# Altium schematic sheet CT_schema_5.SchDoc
size 376 x 215 mm
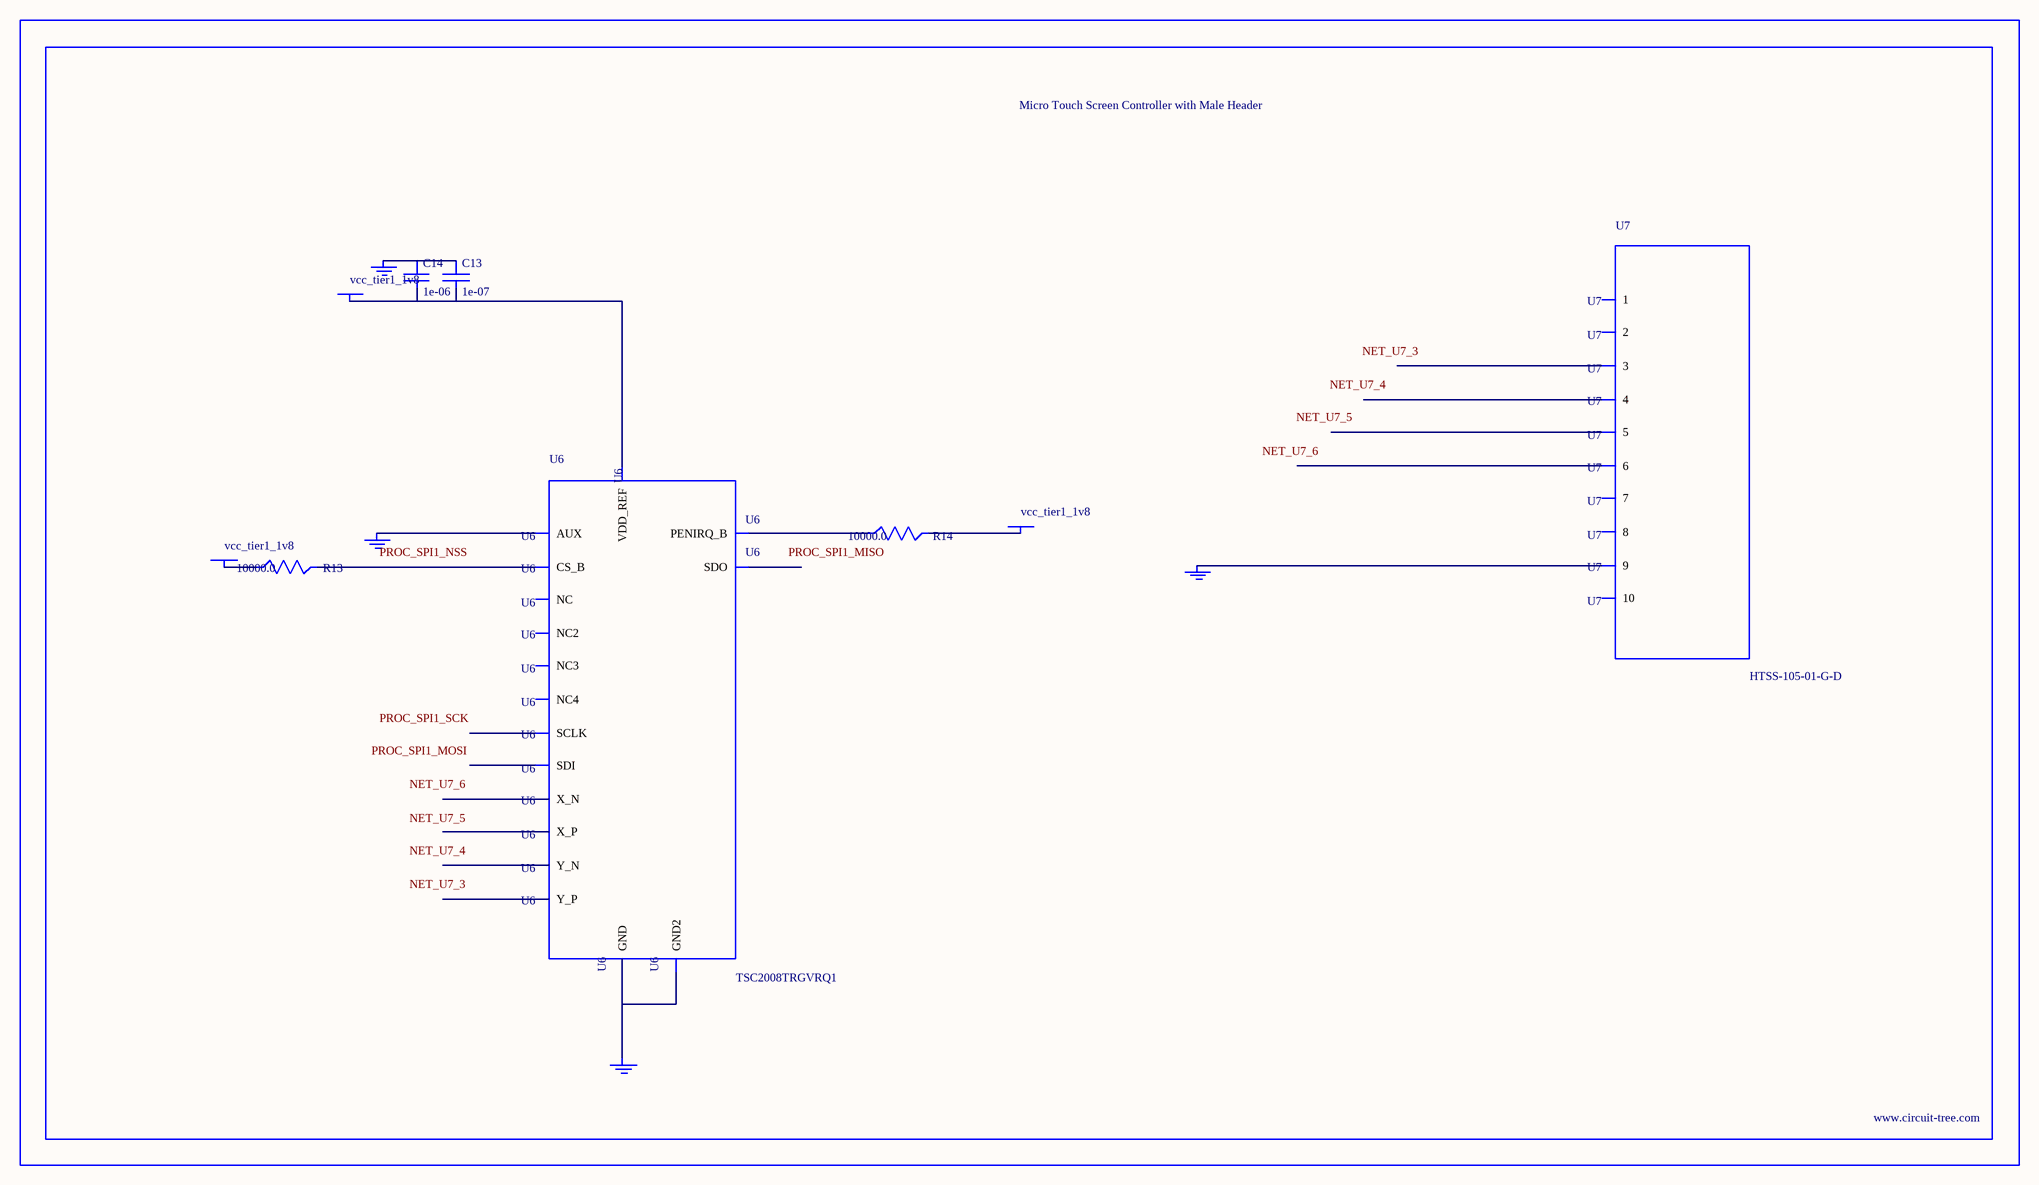
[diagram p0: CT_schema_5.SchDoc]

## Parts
BORDER4  (no value)
C13  1e-07  [C0402]
C14  1e-06  [C0603]
GND_INSTANCE_4_0  (no value)
GND_INSTANCE_4_1  (no value)
GND_INSTANCE_4_2  (no value)
GND_INSTANCE_4_3  (no value)
POWER_INSTANCE_4_0  vcc_tier1_1v8
POWER_INSTANCE_4_1  vcc_tier1_1v8
POWER_INSTANCE_4_2  vcc_tier1_1v8
R13  10000.0  [R0603]
R14  10000.0  [R0603]
U6  TSC2008TRGVRQ1  [QFN65P400X400X100-17N]
U7  HTSS-105-01-G-D  [HTSS-105-01-G-D]

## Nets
NetC13_1: C13.1 C14.1 GND_INSTANCE_4_0.0(GND)
NetC13_2: C13.2 C14.2 POWER_INSTANCE_4_1.0(PWR) U6.5(VDD_REF)
NetGND_INSTANCE_4_1_0: GND_INSTANCE_4_1.0(GND) U6.12(AUX)
NetGND_INSTANCE_4_2_0: GND_INSTANCE_4_2.0(GND) U6.10(GND) U6.17(GND2)
NetGND_INSTANCE_4_3_0: GND_INSTANCE_4_3.0(GND) U7.9
NetPOWER_INSTANCE_4_0_0: POWER_INSTANCE_4_0.0(PWR) R13.1
NetPOWER_INSTANCE_4_2_0: POWER_INSTANCE_4_2.0(PWR) R14.2
NetR13_2: R13.2 U6.3(CS_B)
NetR14_1: R14.1 U6.15(PENIRQ_B)

Not connected (* = marked no-connect by the designer): U6 1(NC) 2(SDI) 4(SCLK) 6(X_P) 7(Y_P) 8(X_N) 9(Y_N) 11(NC2) 13(NC3) 14(NC4) 16(SDO); U7 1 2 3 4 5 6 7 8 10

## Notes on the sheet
- Labels drawn without touching a wire or pin: NET_U7_3, NET_U7_4, NET_U7_5, NET_U7_6, PROC_SPI1_MISO, PROC_SPI1_MOSI, PROC_SPI1_NSS, PROC_SPI1_SCK

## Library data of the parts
BORDER4 = BORDER_PAGE4
C13 = C0402C104K3RACTU
C14 = C0603C105K3RACTU
GND_INSTANCE_4_0-GND_INSTANCE_4_3 = GND
POWER_INSTANCE_4_0-POWER_INSTANCE_4_2 = PWR
R13 R14 = RC0603JR-0710KL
